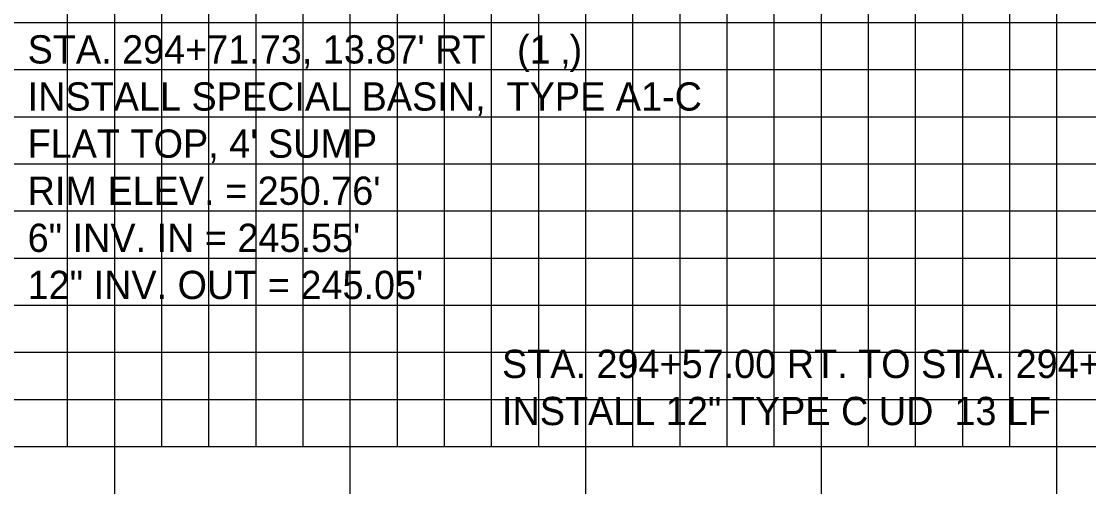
# Model space of a CAD drawing. Extents: x 859352 to 859522, y 366268 to 366378.
# Drawn here: x 859453.15 to 859475.8, y 366306.23 to 366316.26 of the extents above; entities that cross this region are included whole.
import ezdxf

# ---------------------------------------------------------------- set-up
doc = ezdxf.new("R2010")
doc.units = 0
for name, color, linetype in [('D_Drainage_Text', 7, 'Continuous'), ('MAJOR', 7, 'Continuous'), ('MINOR', 7, 'Continuous')]:
    doc.layers.add(name, color=color, linetype=linetype)

msp = doc.modelspace()

# ---------------------------------------------------------------- linework, layer by layer
at = {"layer": 'MAJOR'}
for p, q in [((859455.129, 366307.236), (859455.129, 366327.236)), ((859460.129, 366307.236), (859460.129, 366327.236)), ((859465.129, 366307.236), (859465.129, 366327.236)), ((859470.129, 366307.236), (859470.129, 366327.236)), ((859475.129, 366307.236), (859475.129, 366327.236)), ((859365.129, 366312.236), (859505.129, 366312.236)), ((859365.129, 366307.236), (859505.129, 366307.236)), ((859365.129, 366307.236), (859505.129, 366307.236)), ((859455.129, 366306.234), (859455.129, 366307.236)), ((859460.129, 366306.234), (859460.129, 366307.236)), ((859465.129, 366306.234), (859465.129, 366307.236)), ((859470.129, 366306.234), (859470.129, 366307.236)), ((859475.129, 366306.234), (859475.129, 366307.236))]:
    msp.add_line(p, q, dxfattribs=at)
at = {"layer": 'MINOR'}
for p, q in [((859454.129, 366307.236), (859454.129, 366327.236)), ((859456.129, 366307.236), (859456.129, 366327.236)), ((859457.129, 366307.236), (859457.129, 366327.236)), ((859458.129, 366307.236), (859458.129, 366327.236)), ((859459.129, 366307.236), (859459.129, 366327.236)), ((859461.129, 366307.236), (859461.129, 366327.236)), ((859462.129, 366307.236), (859462.129, 366327.236)), ((859463.129, 366307.236), (859463.129, 366327.236)), ((859464.129, 366307.236), (859464.129, 366327.236)), ((859466.129, 366307.236), (859466.129, 366327.236)), ((859467.129, 366307.236), (859467.129, 366327.236)), ((859468.129, 366307.236), (859468.129, 366327.236)), ((859469.129, 366307.236), (859469.129, 366327.236)), ((859471.129, 366307.236), (859471.129, 366327.236)), ((859472.129, 366307.236), (859472.129, 366327.236)), ((859473.129, 366307.236), (859473.129, 366327.236)), ((859474.129, 366307.236), (859474.129, 366327.236)), ((859365.129, 366316.236), (859505.129, 366316.236)), ((859365.129, 366315.236), (859505.129, 366315.236)), ((859365.129, 366314.236), (859505.129, 366314.236)), ((859365.129, 366313.236), (859505.129, 366313.236)), ((859365.129, 366311.236), (859505.129, 366311.236)), ((859365.129, 366310.236), (859505.129, 366310.236)), ((859365.129, 366309.236), (859505.129, 366309.236)), ((859365.129, 366308.236), (859505.129, 366308.236))]:
    msp.add_line(p, q, dxfattribs=at)

# ---------------------------------------------------------------- texts
at = {"layer": 'D_Drainage_Text'}
for s, p in [("STA. 294+71.73, 13.87' RT   (1 ‚)", (859453.28, 366315.365)), ('INSTALL SPECIAL BASIN,  TYPE A1-C', (859453.28, 366314.365)), ("FLAT TOP, 4' SUMP", (859453.28, 366313.365)), ("RIM ELEV. = 250.76'", (859453.28, 366312.365)), ('6" INV. IN = 245.55\'', (859453.28, 366311.365)), ('12" INV. OUT = 245.05\'', (859453.28, 366310.365)), ('STA. 294+57.00 RT. TO STA. 294+69.73 RT.', (859463.35, 366308.689)), ('INSTALL 12" TYPE C UD  13 LF', (859463.35, 366307.689))]:
    msp.add_text(s, height=0.6, dxfattribs=at).set_placement(p)

doc.saveas('drawing.dxf')
